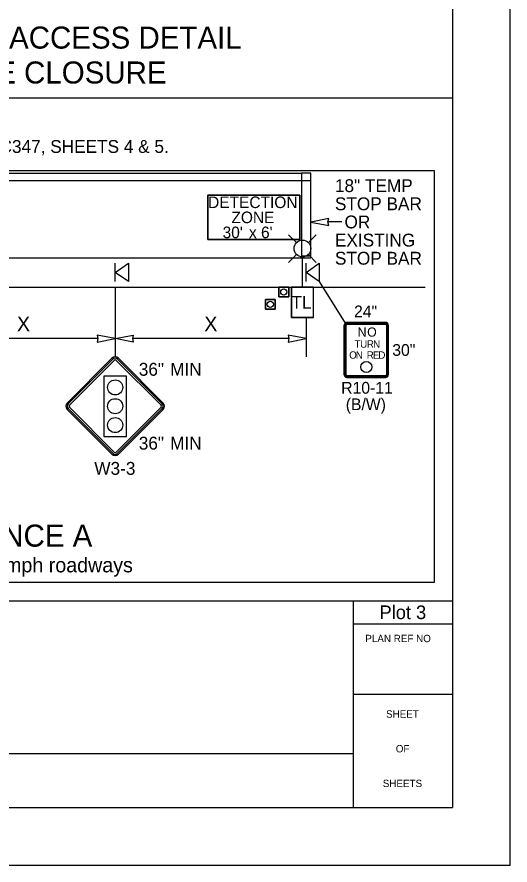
# Model space of a CAD drawing. Extents: x 99979.8 to 100075.7, y 99995 to 100010.7.
# Drawn here: x 100053.379 to 100056.062, y 99999.687 to 100004.304 of the extents above; entities that cross this region are included whole.
import ezdxf

# ---------------------------------------------------------------- set-up
doc = ezdxf.new("R2010")
doc.units = 0
for name, color, linetype in [('Default', 7, 'Continuous'), ('RD_ED_ShoulderPavedEdge', 7, 'Continuous'), ('RD_MK_LineDblYellowCenter', 7, 'Continuous'), ('RD_MK_LineEdgeWhite', 7, 'Continuous'), ('SH_DE_DetailHeading2Text', 7, 'Continuous'), ('SH_GI_GeneralNotesBodyText', 7, 'Continuous'), ('SH_GI_PlotLimits', 7, 'Continuous'), ('SH_GI_SheetBorder', 7, 'Continuous'), ('SH_GI_SheetLocationText', 7, 'Continuous'), ('SH_GI_SheetTextInCells', 7, 'Continuous'), ('TR_SN_ConstructionSigns', 7, 'Continuous'), ('TR_WZ_PortableLightStandard', 7, 'Continuous'), ('TR_WZ_PortableSignMountBlk-Org', 7, 'Continuous'), ('TR_WZ_PortableSignMountBlk-Wht', 7, 'Continuous'), ('TR_WZ_TrafficCone', 7, 'Continuous'), ('TR_WZ_WorkZoneDetails', 7, 'Continuous'), ('TR_WZ_WorkZoneTextCurrent', 7, 'Continuous')]:
    doc.layers.add(name, color=color, linetype=linetype)

msp = doc.modelspace()

# ---------------------------------------------------------------- linework, layer by layer
at = {"layer": 'Default'}
for p, q in [((100053.8959, 100002.4462), (100053.6523, 100002.2026)), ((100054.1743, 100002.2026), (100053.9307, 100002.4462)), ((100053.6523, 100002.1678), (100053.8959, 100001.9241)), ((100053.9307, 100001.9241), (100054.1743, 100002.1678))]:
    msp.add_line(p, q, dxfattribs=at)
msp.add_circle((100055.28, 100002.3989), 0.03, dxfattribs=at)
for centre, start, end in [((100053.9133, 100002.4288), 45, 135), ((100053.6697, 100002.1852), 135, 225), ((100054.1569, 100002.1852), 315, 45), ((100053.9133, 100001.9415), 225, 315)]:
    msp.add_arc(centre, 0.0246, start, end, dxfattribs=at)
at = {"layer": 'RD_ED_ShoulderPavedEdge'}
msp.add_line((100050.65, 100002.8334), (100055.6, 100002.8334), dxfattribs=at)
at = {"layer": 'RD_MK_LineDblYellowCenter'}
for p, q in [((100050.65, 100003.4534), (100054.9276, 100003.4534)), ((100050.65, 100003.4134), (100054.9776, 100003.4134))]:
    msp.add_line(p, q, dxfattribs=at)
at = {"layer": 'RD_MK_LineEdgeWhite'}
msp.add_line((100050.65, 100002.9934), (100054.9776, 100002.9934), dxfattribs=at)
at = {"layer": 'SH_GI_PlotLimits'}
msp.add_lwpolyline([(100039.0625, 99999.6875), (100056.0625, 99999.6875), (100056.0625, 100010.6875), (100039.0625, 100010.6875)], close=True, dxfattribs=at)
at = {"layer": 'SH_GI_SheetBorder'}
for p, q in [((100055.75, 100010.375), (100055.75, 100000)), ((100040, 100001.1259), (100055.75, 100001.1259)), ((100055.2079, 100001.1259), (100055.2079, 100000)), ((100055.2079, 100001.0008), (100055.75, 100001.0008)), ((100055.2079, 100000.6176), (100055.75, 100000.6176)), ((100052.2055, 100000.2955), (100055.2079, 100000.2955)), ((100040, 100000), (100055.75, 100000))]:
    msp.add_line(p, q, dxfattribs=at)
at = {"layer": 'TR_SN_ConstructionSigns'}
for p, q in [((100055.16, 100002.6264), (100055.16, 100002.3564)), ((100055.16, 100002.3564), (100055.16, 100002.6264)), ((100055.16, 100002.6264), (100055.16, 100002.3564)), ((100055.16, 100002.3564), (100055.16, 100002.6264)), ((100055.1637, 100002.6264), (100055.1637, 100002.3564)), ((100055.17, 100002.3564), (100055.17, 100002.6264)), ((100055.385, 100002.6414), (100055.175, 100002.6414)), ((100055.175, 100002.6414), (100055.385, 100002.6414)), ((100055.385, 100002.6414), (100055.175, 100002.6414)), ((100055.175, 100002.6414), (100055.385, 100002.6414)), ((100055.385, 100002.6376), (100055.175, 100002.6376)), ((100055.175, 100002.6314), (100055.385, 100002.6314)), ((100055.39, 100002.6264), (100055.39, 100002.3564)), ((100055.3962, 100002.3564), (100055.3962, 100002.6264)), ((100055.4, 100002.3564), (100055.4, 100002.6264)), ((100055.4, 100002.6264), (100055.4, 100002.3564)), ((100055.4, 100002.3564), (100055.4, 100002.6264)), ((100055.4, 100002.6264), (100055.4, 100002.3564)), ((100053.6523, 100002.2026), (100053.8959, 100002.4462)), ((100053.9007, 100002.4413), (100053.6571, 100002.1977)), ((100054.1695, 100002.1977), (100053.9258, 100002.4413)), ((100053.9307, 100002.4462), (100054.1743, 100002.2026)), ((100053.6639, 100002.191), (100053.9075, 100002.4346)), ((100053.9191, 100002.4346), (100054.1627, 100002.191)), ((100053.9748, 100002.3492), (100053.8518, 100002.3492)), ((100053.8518, 100002.3492), (100053.8518, 100002.0211)), ((100053.9748, 100002.0211), (100053.9748, 100002.3492)), ((100055.385, 100002.3514), (100055.175, 100002.3514)), ((100055.175, 100002.3451), (100055.385, 100002.3451)), ((100055.175, 100002.3414), (100055.385, 100002.3414)), ((100055.385, 100002.3414), (100055.175, 100002.3414)), ((100055.175, 100002.3414), (100055.385, 100002.3414)), ((100055.385, 100002.3414), (100055.175, 100002.3414)), ((100053.8959, 100001.9241), (100053.6523, 100002.1678)), ((100053.6571, 100002.1726), (100053.9007, 100001.929)), ((100053.9075, 100001.9357), (100053.6639, 100002.1794)), ((100054.1627, 100002.1794), (100053.9191, 100001.9357)), ((100053.9258, 100001.929), (100054.1695, 100002.1726)), ((100054.1743, 100002.1678), (100053.9307, 100001.9241)), ((100053.8518, 100002.0211), (100053.9748, 100002.0211))]:
    msp.add_line(p, q, dxfattribs=at)
for centre in [(100053.9133, 100002.2877), (100053.9133, 100002.2877), (100053.9133, 100002.1852), (100053.9133, 100002.1852), (100053.9133, 100002.0826), (100053.9133, 100002.0826)]:
    msp.add_circle(centre, 0.041, dxfattribs=at)
for centre, radius, start, end in [((100055.175, 100002.6264), 0.015, 90, 180), ((100055.175, 100002.6264), 0.015, 90, 180), ((100055.175, 100002.6264), 0.015, 90, 180), ((100055.175, 100002.6264), 0.015, 90, 180), ((100055.175, 100002.6264), 0.0112, 90, 180), ((100055.175, 100002.6264), 0.005, 90, 180), ((100055.385, 100002.6264), 0.015, 0, 90), ((100055.385, 100002.6264), 0.015, 0, 90), ((100055.385, 100002.6264), 0.015, 0, 90), ((100055.385, 100002.6264), 0.015, 0, 90), ((100055.385, 100002.6264), 0.0112, 0, 90), ((100055.385, 100002.6264), 0.005, 0, 90), ((100053.9133, 100002.4288), 0.0246, 45, 135), ((100053.9133, 100002.4288), 0.0178, 45, 135), ((100053.9133, 100002.4288), 0.0082, 45, 135), ((100055.175, 100002.3564), 0.015, 180, 270), ((100055.175, 100002.3564), 0.015, 180, 270), ((100055.175, 100002.3564), 0.015, 180, 270), ((100055.175, 100002.3564), 0.015, 180, 270), ((100055.175, 100002.3564), 0.0112, 180, 270), ((100055.175, 100002.3564), 0.005, 180, 270), ((100055.385, 100002.3564), 0.015, 270, 0), ((100055.385, 100002.3564), 0.015, 270, 0), ((100055.385, 100002.3564), 0.015, 270, 0), ((100055.385, 100002.3564), 0.0112, 270, 0), ((100055.385, 100002.3564), 0.005, 270, 0), ((100055.385, 100002.3564), 0.015, 270, 0), ((100053.6697, 100002.1852), 0.0246, 135, 225), ((100053.6697, 100002.1852), 0.0178, 135, 225), ((100053.6697, 100002.1852), 0.0082, 135, 225), ((100054.1569, 100002.1852), 0.0082, 315, 45), ((100054.1569, 100002.1852), 0.0178, 315, 45), ((100054.1569, 100002.1852), 0.0246, 315, 45), ((100053.9133, 100001.9415), 0.0082, 225, 315), ((100053.9133, 100001.9415), 0.0246, 225, 315), ((100053.9133, 100001.9415), 0.0178, 225, 315)]:
    msp.add_arc(centre, radius, start, end, dxfattribs=at)
at = {"layer": 'TR_WZ_PortableLightStandard'}
for p, q in [((100054.9002, 100003.0759), (100054.8571, 100003.119)), ((100054.965, 100003.0759), (100055.0079, 100003.119)), ((100054.9002, 100003.0112), (100054.8571, 100002.9681)), ((100054.9326, 100002.8334), (100054.9326, 100002.9978)), ((100054.965, 100003.0112), (100055.0079, 100002.9681)), ((100054.8726, 100002.6674), (100054.8726, 100002.8334)), ((100054.9926, 100002.8334), (100054.8726, 100002.8334)), ((100054.8726, 100002.8334), (100054.8726, 100002.6674)), ((100054.9926, 100002.6674), (100054.9926, 100002.8334)), ((100054.9926, 100002.6674), (100054.9926, 100002.8334)), ((100054.9926, 100002.6674), (100054.8726, 100002.6674))]:
    msp.add_line(p, q, dxfattribs=at)
for points in [[(100054.9926, 100002.8334), (100054.9326, 100002.8334), (100054.8726, 100002.8334)], [(100054.8726, 100002.6674), (100054.9326, 100002.6674), (100054.9926, 100002.6674)]]:
    msp.add_lwpolyline(points, dxfattribs=at)
msp.add_circle((100054.9325, 100003.0436), 0.0457, dxfattribs=at)
msp.add_circle((100054.9325, 100003.0436), 0.0457, dxfattribs=at)
at = {"layer": 'TR_WZ_PortableSignMountBlk-Org'}
msp.add_line((100053.9133, 100002.8634), (100053.9133, 100002.9634), dxfattribs=at)
msp.add_lwpolyline([(100053.9133, 100002.9133), (100053.9851, 100002.9634), (100053.9851, 100002.8634)], close=True, dxfattribs=at)
at = {"layer": 'TR_WZ_PortableSignMountBlk-Wht'}
msp.add_line((100054.9526, 100002.8634), (100054.9526, 100002.9634), dxfattribs=at)
msp.add_lwpolyline([(100054.9526, 100002.9133), (100055.0244, 100002.9634), (100055.0244, 100002.8634)], close=True, dxfattribs=at)
at = {"layer": 'TR_WZ_TrafficCone'}
for points in [[(100054.8576, 100002.7801), (100054.8576, 100002.8334), (100054.8042, 100002.8334), (100054.8042, 100002.7801), (100054.8576, 100002.7801)], [(100054.8042, 100002.7801), (100054.8042, 100002.8334), (100054.8576, 100002.8334), (100054.8576, 100002.7801), (100054.8042, 100002.7801)], [(100054.7842, 100002.7134), (100054.7842, 100002.7667), (100054.7309, 100002.7667), (100054.7309, 100002.7134), (100054.7842, 100002.7134)], [(100054.7309, 100002.7134), (100054.7309, 100002.7667), (100054.7842, 100002.7667), (100054.7842, 100002.7134), (100054.7309, 100002.7134)]]:
    msp.add_lwpolyline(points, dxfattribs=at)
for centre in [(100054.8309, 100002.8067), (100054.7576, 100002.7401)]:
    msp.add_circle(centre, 0.0167, dxfattribs=at)
at = {"layer": 'TR_WZ_WorkZoneDetails'}
for p, q in [((100055.75, 100003.862), (100050.5, 100003.862)), ((100055.1475, 100003.1884), (100055.0713, 100003.1884)), ((100055.0244, 100002.8634), (100055.1643, 100002.637)), ((100053.9133, 100002.8334), (100053.9133, 100002.4534)), ((100054.9526, 100002.6674), (100054.9526, 100002.4534)), ((100053.8195, 100002.5534), (100053.007, 100002.5534)), ((100054.8588, 100002.5534), (100054.007, 100002.5534))]:
    msp.add_line(p, q, dxfattribs=at)
for points in [[(100054.9276, 100003.0034), (100054.9776, 100003.0034), (100054.9776, 100003.4534), (100054.9276, 100003.4534), (100054.9276, 100003.0034)], [(100054.9276, 100003.0034), (100054.9776, 100003.0034), (100054.9776, 100003.4534), (100054.9276, 100003.4534), (100054.9276, 100003.0034)], [(100054.4176, 100003.3334), (100054.9176, 100003.3334), (100054.9176, 100003.0934), (100054.4176, 100003.0934), (100054.4176, 100003.3334)], [(100054.4176, 100003.0934), (100054.9176, 100003.0934), (100054.9176, 100003.3334), (100054.4176, 100003.3334), (100054.4176, 100003.0934)]]:
    msp.add_lwpolyline(points, dxfattribs=at)
for points in [[(100054.9776, 100003.1876), (100055.076, 100003.1692), (100055.0713, 100003.1884), (100055.0757, 100003.2077)], [(100053.9133, 100002.5534), (100053.815, 100002.5727), (100053.8195, 100002.5534), (100053.815, 100002.5341)], [(100053.9133, 100002.5534), (100054.0116, 100002.5727), (100054.007, 100002.5534), (100054.0116, 100002.5341)], [(100054.9526, 100002.5534), (100054.8543, 100002.5727), (100054.8588, 100002.5534), (100054.8543, 100002.5341)]]:
    msp.add_lwpolyline(points, close=True, dxfattribs=at)
at = {"layer": 'TR_WZ_WorkZoneTextCurrent'}
msp.add_lwpolyline([(100050.6, 100003.4685), (100055.65, 100003.4685), (100055.65, 100001.2259), (100050.6, 100001.2259)], close=True, dxfattribs=at)

# ---------------------------------------------------------------- texts
at = {"layer": 'Default'}
for s, height, p in [('N', 0.05, (100055.2331, 100002.5639)), ('O', 0.05, (100055.2848, 100002.5639)), ('T', 0.04, (100055.2159, 100002.5039)), ('U', 0.04, (100055.2465, 100002.5039)), ('R', 0.04, (100055.283, 100002.5039)), ('N', 0.04, (100055.3169, 100002.5039)), ('O', 0.04, (100055.187, 100002.4439)), ('N', 0.04, (100055.2226, 100002.4439)), ('R', 0.04, (100055.2826, 100002.4439)), ('E', 0.04, (100055.3154, 100002.4439)), ('D', 0.04, (100055.3457, 100002.4439))]:
    msp.add_text(s, height=height, dxfattribs=at).set_placement(p)
at = {"layer": 'SH_DE_DetailHeading2Text'}
for s, p in [('DRIVEWAY OR BUSINESS ACCESS DETAIL', (100051.2936, 100004.132)), ('OPPOSITE OF LANE CLOSURE', (100051.8211, 100003.942)), ('SIGN SEQUENCE A', (100052.2998, 100001.4208))]:
    msp.add_text(s, height=0.12, rotation=360, dxfattribs=at).set_placement(p)
at = {"layer": 'SH_GI_GeneralNotesBodyText'}
msp.add_text('18. FOR LEGEND, TABLES, AND ADDITIONAL NOTES: SEE TC347, SHEETS 4 & 5.', height=0.07, rotation=360, dxfattribs=at).set_placement((100050.6, 100003.5642))
at = {"layer": 'SH_GI_SheetBorder'}
msp.add_text('PLAN REF NO', height=0.040032, dxfattribs=at).set_placement((100055.2747, 100000.9008))
at = {"layer": 'SH_GI_SheetLocationText'}
msp.add_text('Plot 3', height=0.07425, dxfattribs=at).set_placement((100055.3521, 100001.0262))
at = {"layer": 'SH_GI_SheetTextInCells'}
for s, p in [('SHEET', (100055.3877, 100000.4896)), ('OF', (100055.4406, 100000.3008)), ('SHEETS', (100055.3698, 100000.112))]:
    msp.add_text(s, height=0.04003, dxfattribs=at).set_placement(p)
at = {"layer": 'TR_SN_ConstructionSigns'}
for s, height, p in [('24"', 0.064, (100055.2135, 100002.6694)), ('30"', 0.064, (100055.4215, 100002.4594)), ('36"', 0.07, (100054.0417, 100002.3512)), ('MIN', 0.07, (100054.2123, 100002.3512)), ('R10-11', 0.064, (100055.1435, 100002.2534)), ('(B/W)', 0.064, (100055.1683, 100002.1638)), ('36"', 0.07, (100054.0417, 100001.9491)), ('MIN', 0.07, (100054.2123, 100001.9491)), ('W3-3', 0.07, (100053.7997, 100001.8119))]:
    msp.add_text(s, height=height, rotation=360, dxfattribs=at).set_placement(p)
at = {"layer": 'TR_WZ_PortableLightStandard'}
msp.add_text('TL', height=0.07, dxfattribs=at).set_placement((100054.8724, 100002.7154))
at = {"layer": 'TR_WZ_WorkZoneDetails'}
for s, p in [('DETECTION', (100054.4189, 100003.2638)), ('ZONE', (100054.5461, 100003.1819)), ("30'", (100054.4979, 100003.1)), ("x 6'", (100054.6415, 100003.1))]:
    msp.add_text(s, height=0.063, dxfattribs=at).set_placement(p)
at = {"layer": 'TR_WZ_WorkZoneTextCurrent'}
for s, height, p in [('18" TEMP', 0.07, (100055.1094, 100003.351)), ('STOP BAR', 0.07, (100055.1094, 100003.2522)), ('  OR', 0.07, (100055.1094, 100003.1534)), ('EXISTING', 0.07, (100055.1094, 100003.0546)), ('STOP BAR', 0.07, (100055.1094, 100002.9558)), ('48"x48" signs required on 45+ mph roadways', 0.08, (100051.8551, 100001.2808))]:
    msp.add_text(s, height=height, dxfattribs=at).set_placement(p)
for p in [(100053.3786, 100002.5934), (100054.3982, 100002.5934)]:
    msp.add_text('X', height=0.08, rotation=360, dxfattribs=at).set_placement(p)

doc.saveas('drawing.dxf')
